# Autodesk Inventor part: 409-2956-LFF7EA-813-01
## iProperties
Created: 2010-11
Part Number: 409-2956-LFF7EA-813-01
Material: 3/8" OD TUBE - SS
Description: PT TUBING
Document SubType Name: Modeling
Designer: S. Boerckel
Engineer: Steve Boerckel
Mass: 967.015 g
Surface Area: 2094.74 cm^2
Volume: 119.68 cm^3
Density: 8.08 g/cm^3
Length: 156.546 in
Author: S. Boerckel
Revision Number: 0
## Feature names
1. Sweep1
2. Sweep2
